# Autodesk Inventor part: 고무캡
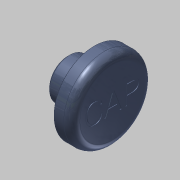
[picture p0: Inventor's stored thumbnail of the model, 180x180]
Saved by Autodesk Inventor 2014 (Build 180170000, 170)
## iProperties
Created: 2017-06
Part Number: 고무캡
Material: 고무
Document SubType Name: Modeling
Designer: mduedu
Density: 1 g/cm^3
Appearance: Rubber - Blue - Version 1.1
Author: mduedu
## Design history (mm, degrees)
sketch "스케치1"
  geometry: L1 (0, 0)-(11, 0); L2 (11, 0)-(11, 10); L3 (11, 10)-(6.5, 10); L4 (0, 5)-(0, 0); L5 (0, 5)-(6, 5); L6 (6, 5)-(6, 9); L7 (6, 9)-(6.5, 9); L8 (6.5, 9)-(6.5, 10)
  constraints: 16 end point, 2 horizontal, 2 parallel, 2 perpendicular, 2 point on line, 1 vertical
  dimensions: "d0" = 20 diameter of L3 L1; "d2" = 10 diameter of L5 L1; "d6" = 5 distance between parallel lines of L2 L6; "d7" = 0.5 distance between parallel lines of L8 L6; "d8" = 18 diameter of L7 L1; "d9" = 6 distance between parallel lines of L6 L4
revolve "회전1" sketch "스케치1" stored, may be unused: angle "d10" = 90 deg
hole "구멍1" diameter "d22" = 7; stored, may be unused: countersink angle "d26" = 90 deg, drill point angle "d28" = 0 deg; dims "d23" = 6, "d24" = 4, "d25" = 2, "d27" = 6, "d32" = 10, "d33" = 10
chamfer "모따기1" distance "d13" = 0.5; stored, may be unused: second distance "d14" = 2, angle "d15" = 45 deg
fillet "모깎기3" dims "d29" = 1
fillet "모깎기1" dims "d16" = 0.1
fillet "모깎기2" dims "d17" = 2
sketch "스케치3"
  geometry: 2 further points
  constraints: 1 coincident, 1 other
feature "엠보싱1" sketch "스케치3" dims "d18" = 0.2, "d19" = 0
node "솔리드1"
